// Mitsubishi GX Works2 project: FX2N PLC与丹佛斯VT2800通讯   PLC: FX2N/FX2NC

PROGRAM MAIN
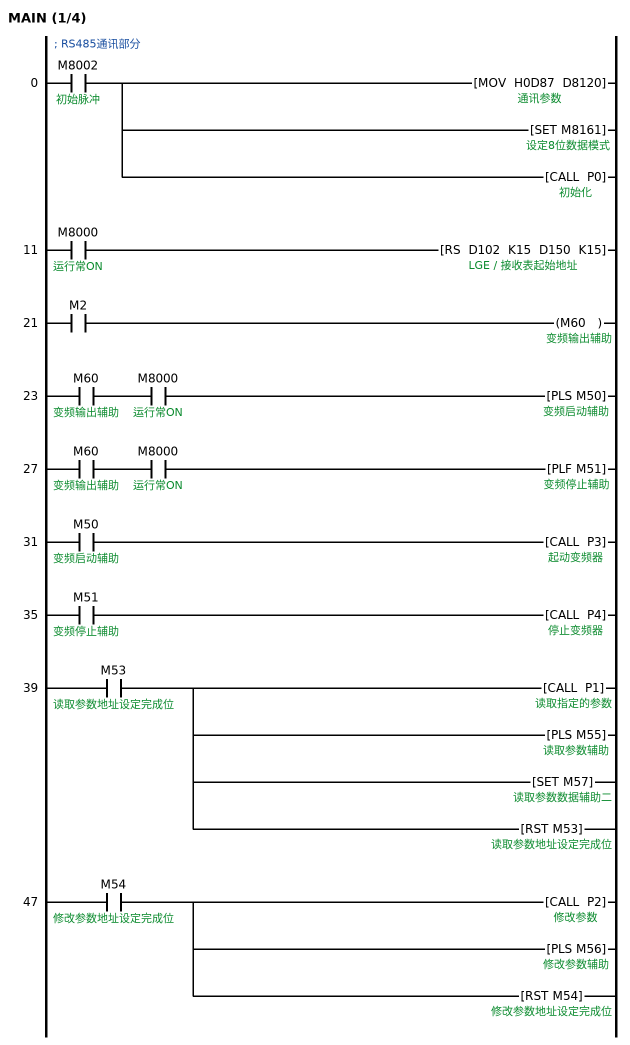
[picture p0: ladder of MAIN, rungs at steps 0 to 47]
; RS485通讯部分
0     LD      M8002  ; 初始脉冲
      MOV     H0D87 D8120  ; 通讯参数
      SET     M8161  ; 设定8位数据模式
      CALL    P0  ; 初始化
11    LD      M8000  ; 运行常ON
      RS      D102 K15 D150 K15  ; LGE / 接收表起始地址
21    LD      M2
      OUT     M60  ; 变频输出辅助
23    LD      M60  ; 变频输出辅助
      AND     M8000  ; 运行常ON
      PLS     M50  ; 变频启动辅助
27    LD      M60  ; 变频输出辅助
      AND     M8000  ; 运行常ON
      PLF     M51  ; 变频停止辅助
31    LD      M50  ; 变频启动辅助
      CALL    P3  ; 起动变频器
35    LD      M51  ; 变频停止辅助
      CALL    P4  ; 停止变频器
39    LD      M53  ; 读取参数地址设定完成位
      CALL    P1  ; 读取指定的参数
      PLS     M55  ; 读取参数辅助
      SET     M57  ; 读取参数数据辅助二
      RST     M53  ; 读取参数地址设定完成位
47    LD      M54  ; 修改参数地址设定完成位
      CALL    P2  ; 修改参数
      PLS     M56  ; 修改参数辅助
      RST     M54  ; 修改参数地址设定完成位
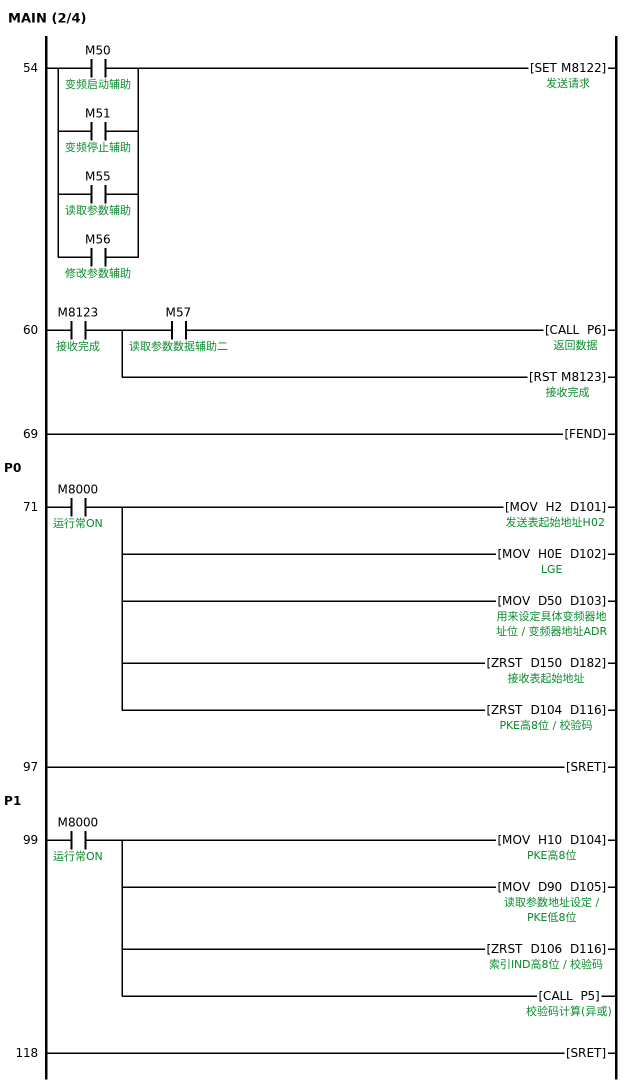
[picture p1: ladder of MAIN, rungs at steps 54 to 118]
54    LD      M50  ; 变频启动辅助
      OR      M51  ; 变频停止辅助
      OR      M55  ; 读取参数辅助
      OR      M56  ; 修改参数辅助
      SET     M8122  ; 发送请求
60    LD      M8123  ; 接收完成
      MPS
      AND     M57  ; 读取参数数据辅助二
      CALL    P6  ; 返回数据
      MPP
      RST     M8123  ; 接收完成
69    FEND
      P0
71    LD      M8000  ; 运行常ON
      MOV     H2 D101  ; 发送表起始地址H02
      MOV     H0E D102
      MOV     D50 D103  ; 用来设定具体变频器地址位 / 变频器地址ADR
      ZRST    D150 D182
      ZRST    D104 D116  ; PKE高8位 / 校验码
97    SRET
      P1
99    LD      M8000  ; 运行常ON
      MOV     H10 D104
      MOV     D90 D105  ; 读取参数地址设定 / PKE低8位
      ZRST    D106 D116  ; 索引IND高8位
      CALL    P5  ; 校验码计算(异或)
118   SRET
; 
      P2
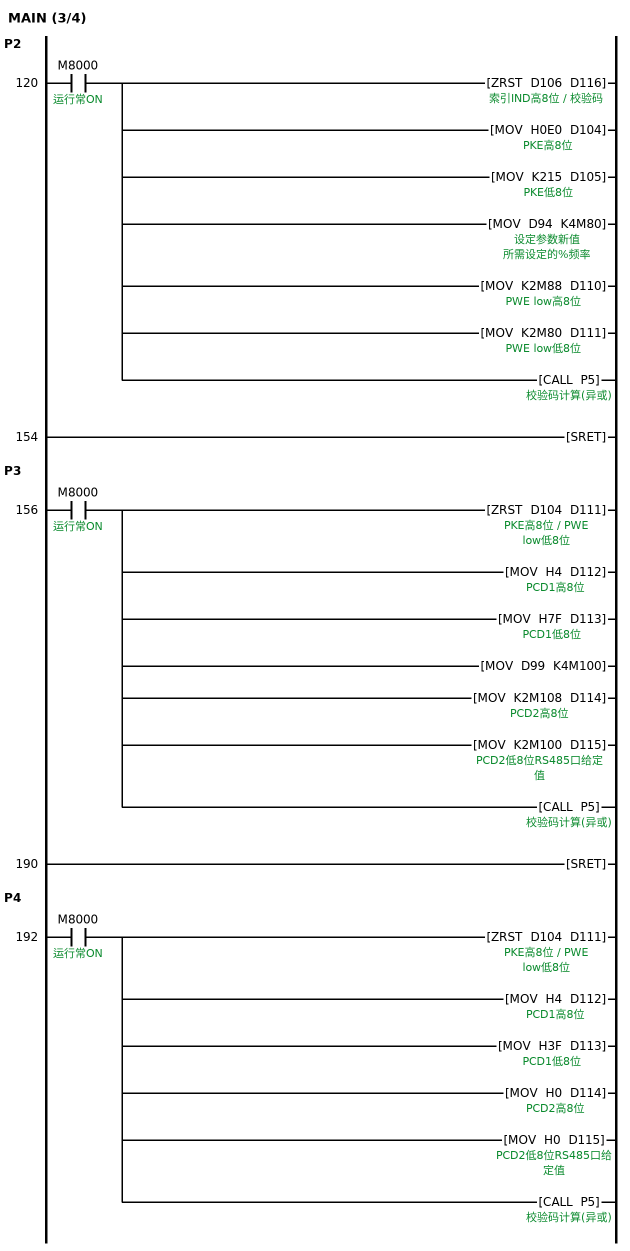
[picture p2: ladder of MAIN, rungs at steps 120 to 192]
120   LD      M8000  ; 运行常ON
      ZRST    D106 D116
      MOV     H0E0 D104
      MOV     K215 D105
        [note] K215为D92为修改参数地址设定
      MOV     D94 K4M80  ; 设定参数新值 所需设定的%频率
      MOV     K2M88 D110  ; PWE low高8位
      MOV     K2M80 D111  ; PWE low低8位
      CALL    P5
154   SRET
      P3
156   LD      M8000  ; 运行常ON
      ZRST    D104 D111
      MOV     H4 D112  ; PCD1高8位
      MOV     H7F D113  ; PCD1低8位
      MOV     D99 K4M100
      MOV     K2M108 D114  ; PCD2高8位
      MOV     K2M100 D115  ; PCD2低8位RS485口给定值
      CALL    P5
190   SRET
      P4
192   LD      M8000  ; 运行常ON
      ZRST    D104 D111
      MOV     H4 D112
      MOV     H3F D113
      MOV     H0 D114
      MOV     H0 D115
      CALL    P5
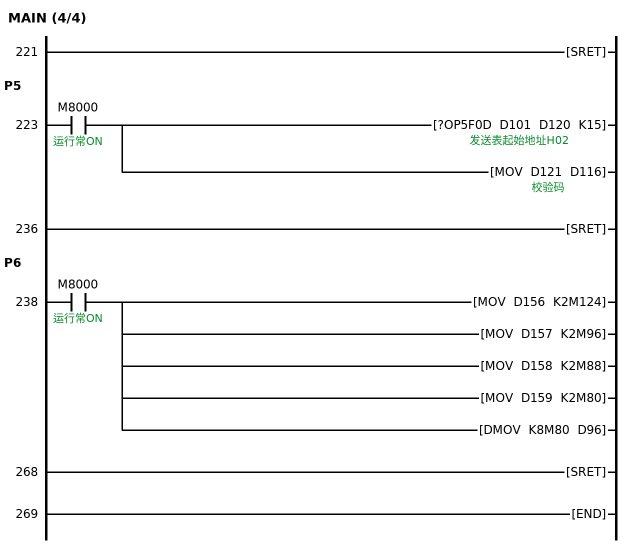
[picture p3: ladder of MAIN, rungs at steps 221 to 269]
221   SRET
      P5
223   LD      M8000  ; 运行常ON
      ?OP5F0D D101 D120 K15
      MOV     D121 D116
236   SRET
      P6
238   LD      M8000  ; 运行常ON
      MOV     D156 K2M124
      MOV     D157 K2M96
      MOV     D158 K2M88
      MOV     D159 K2M80
      DMOV    K8M80 D96
268   SRET
269   END
END_PROGRAM
